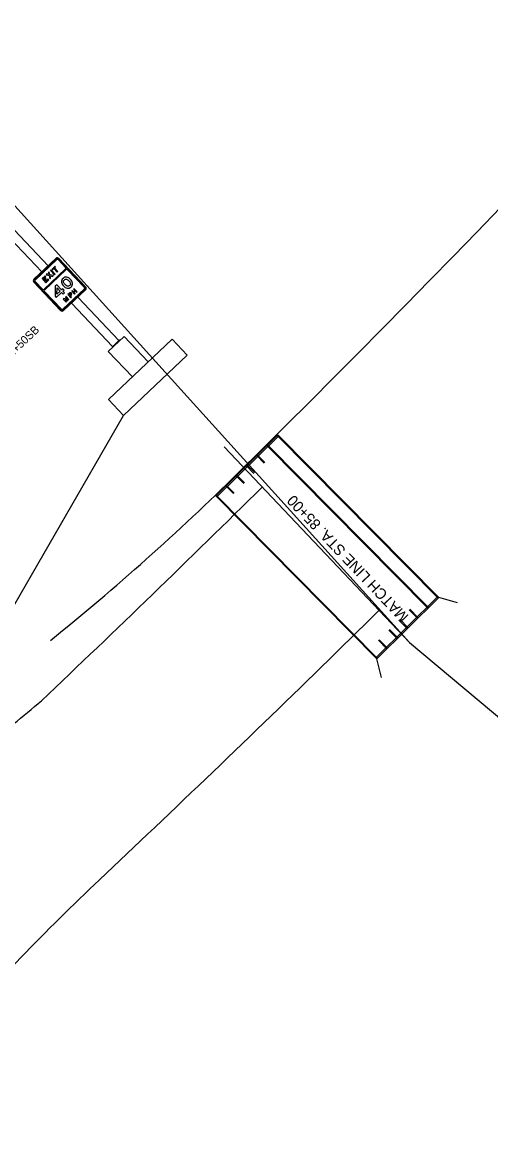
# Model space of a CAD drawing. Extents: x 1289840 to 1295361, y 220865 to 226414.
# Drawn here: x 1294139 to 1294486, y 224717 to 225540 of the extents above; entities that cross this region are included whole.
import ezdxf

# ---------------------------------------------------------------- set-up
doc = ezdxf.new("R2010")
doc.units = 0
for name, color, linetype in [('5', 7, 'Continuous'), ('Plan Notes', 7, 'Continuous'), ('R_Annotation', 7, 'Continuous'), ('R_Drainage', 7, 'Continuous'), ('R_No Plot', 7, 'Continuous'), ('R_Proposed Road', 7, 'Continuous'), ('S_MISC_STRUCTURES', 7, 'Continuous'), ('SIGNS', 7, 'Continuous')]:
    doc.layers.add(name, color=color, linetype=linetype)

msp = doc.modelspace()

# ---------------------------------------------------------------- linework, layer by layer
at = {"layer": '5'}
msp.add_line((1294425.84, 225079.29), (1294288.26, 225224.45), dxfattribs=at)
at = {"layer": 'R_Drainage'}
for p, q in [((1294328.06, 225233.41), (1294282.12, 225188.02)), ((1294328.76, 225232.7), (1294282.82, 225187.31)), ((1294327.64, 225233), (1294446.96, 225112.23)), ((1294447.38, 225112.64), (1294328.06, 225233.41)), ((1294320, 225225.44), (1294439.31, 225104.68)), ((1294320.53, 225225.97), (1294439.85, 225105.2)), ((1294312.47, 225218.01), (1294318.06, 225212.34)), ((1294312.88, 225218.42), (1294318.48, 225212.75)), ((1294297.71, 225203.42), (1294303.3, 225197.76)), ((1294304.82, 225210.45), (1294310.42, 225204.79)), ((1294305.35, 225210.98), (1294310.95, 225205.31)), ((1294289.64, 225195.46), (1294295.24, 225189.79)), ((1294290.06, 225195.87), (1294295.66, 225190.2)), ((1294297.17, 225202.9), (1294302.77, 225197.23)), ((1294401.43, 225067.25), (1294282.12, 225188.02)), ((1294282.53, 225188.43), (1294401.85, 225067.66)), ((1294446.67, 225113.35), (1294400.73, 225067.96)), ((1294447.38, 225112.64), (1294401.43, 225067.25)), ((1294461.3, 225108.82), (1294447.38, 225112.64)), ((1294424.67, 225090.21), (1294418.48, 225096.48)), ((1294431.79, 225097.24), (1294425.6, 225103.5)), ((1294432.2, 225097.65), (1294426.01, 225103.91)), ((1294416.49, 225082.13), (1294410.3, 225088.39)), ((1294417.02, 225082.65), (1294410.83, 225088.92)), ((1294424.14, 225089.68), (1294417.95, 225095.95)), ((1294408.96, 225074.69), (1294402.77, 225080.95)), ((1294409.38, 225075.1), (1294403.19, 225081.36)), ((1294405.09, 225053.28), (1294401.43, 225067.25))]:
    msp.add_line(p, q, dxfattribs=at)
for centre, radius, start, end in [((1286302.67, 233302.78), 11380.16, 314.636938, 322.750132), ((1292982.97, 226537.28), 1872.36, 308.9286, 314.63694)]:
    msp.add_arc(centre, radius, start, end, dxfattribs=at)
at = {"layer": 'R_No Plot'}
msp.add_lwpolyline([(1293463.51, 223873.73), (1293451.02, 223927.27), (1293084.88, 224313.59), (1293049.18, 224285.32), (1292886.4, 224457.07), (1293263.31, 224814.29), (1294021.34, 225526.85), (1294425.84, 225079.29), (1294588.32, 224942.91), (1294719.88, 224769.04), (1294177.05, 224254.57), (1293865.38, 223959.18), (1293708.84, 223976.93), (1293583.27, 224083.83), (1293485.04, 224003.92), (1293450.74, 223971.87), (1293580.16, 223892.04), (1293536.69, 223828.17)], close=True, dxfattribs=at)
at = {"layer": 'R_Proposed Road'}
msp.add_line((1294231.45, 224936.96), (1294195.79, 224903.17), dxfattribs=at)
for centre, radius, start, end in [((1286302.67, 233302.78), 11400.16, 313.519633, 314.664888), ((1286302.67, 233302.78), 11526.16, 313.463611, 314.651754), ((1292930.84, 226486.2), 1896.36, 308.48879, 310.12096), ((1295500.29, 223526.77), 1896.36, 133.46361, 138.41583)]:
    msp.add_arc(centre, radius, start, end, dxfattribs=at)
at = {"layer": 'S_MISC_STRUCTURES'}
for p, q in [((1294157.72, 225358.81), (1294084.18, 225436.41)), ((1294153.01, 225354.34), (1294079.46, 225431.94)), ((1294210.26, 225303.38), (1294180.08, 225335.22)), ((1294205.54, 225298.91), (1294175.36, 225330.75)), ((1294202.32, 225295.26), (1294214.11, 225306.43)), ((1294202.51, 225259.62), (1294249.69, 225304.33)), ((1294205.17, 225298.55), (1294210.67, 225303.76)), ((1294205.44, 225298.26), (1294210.94, 225303.48)), ((1294210.74, 225303.29), (1294205.63, 225298.45)), ((1294210.94, 225303.48), (1294210.67, 225303.76)), ((1294232, 225287.56), (1294214.11, 225306.43)), ((1294249.69, 225304.33), (1294260.87, 225292.54)), ((1294220.2, 225276.39), (1294202.32, 225295.26)), ((1294205.44, 225298.26), (1294205.17, 225298.55)), ((1294205.63, 225298.45), (1294205.66, 225298.42)), ((1294213.69, 225247.82), (1294260.87, 225292.54)), ((1294202.51, 225259.62), (1294213.69, 225247.82)), ((1294052.63, 224968.64), (1294213.69, 225247.82))]:
    msp.add_line(p, q, dxfattribs=at)
msp.add_lwpolyline([(1294205.66, 225298.42), (1294210.77, 225303.27), (1294210.74, 225303.29)], dxfattribs=at)
at = {"layer": 'SIGNS'}
for p, q in [((1294163.49, 225364.28), (1294147.24, 225348.87)), ((1294163.49, 225364.28), (1294147.24, 225348.87)), ((1294147.51, 225348.58), (1294163.77, 225363.99)), ((1294148.07, 225348.19), (1294164.13, 225363.41)), ((1294163.49, 225364.28), (1294163.49, 225364.28)), ((1294163.49, 225364.28), (1294163.49, 225364.28)), ((1294165.07, 225363.39), (1294170.76, 225357.39)), ((1294165.47, 225363.94), (1294185.28, 225343.04)), ((1294185.57, 225343.32), (1294165.76, 225364.22)), ((1294185.57, 225343.32), (1294165.76, 225364.22)), ((1294155.43, 225351.39), (1294153.25, 225349.31)), ((1294155.43, 225351.39), (1294153.25, 225349.31)), ((1294170.74, 225356.45), (1294154.67, 225341.22)), ((1294155.13, 225340.74), (1294171.19, 225355.96)), ((1294155.93, 225350.86), (1294155.43, 225351.39)), ((1294155.93, 225350.86), (1294155.43, 225351.39)), ((1294156.88, 225352.75), (1294156.33, 225352.23)), ((1294156.88, 225352.75), (1294156.33, 225352.23)), ((1294156.33, 225352.23), (1294158.52, 225351.66)), ((1294156.33, 225352.23), (1294158.52, 225351.66)), ((1294158.37, 225352.37), (1294156.88, 225352.75)), ((1294158.37, 225352.37), (1294156.88, 225352.75)), ((1294158.62, 225354.4), (1294158.07, 225353.88)), ((1294158.62, 225354.4), (1294158.07, 225353.88)), ((1294158.07, 225353.88), (1294158.37, 225352.37)), ((1294158.07, 225353.88), (1294158.37, 225352.37)), ((1294158.52, 225351.66), (1294159.05, 225349.04)), ((1294158.52, 225351.66), (1294159.05, 225349.04)), ((1294159.07, 225352.19), (1294158.62, 225354.4)), ((1294159.07, 225352.19), (1294158.62, 225354.4)), ((1294161.66, 225351.52), (1294159.07, 225352.19)), ((1294161.66, 225351.52), (1294159.07, 225352.19)), ((1294159.6, 225349.56), (1294159.21, 225351.49)), ((1294159.21, 225351.49), (1294161.11, 225350.99)), ((1294159.6, 225349.56), (1294159.21, 225351.49)), ((1294159.21, 225351.49), (1294161.11, 225350.99)), ((1294160, 225355.71), (1294159.47, 225355.21)), ((1294160, 225355.71), (1294159.47, 225355.21)), ((1294159.47, 225355.21), (1294162.35, 225352.18)), ((1294159.47, 225355.21), (1294162.35, 225352.18)), ((1294162.88, 225352.67), (1294160, 225355.71)), ((1294162.88, 225352.67), (1294160, 225355.71)), ((1294162.88, 225358.45), (1294160.65, 225356.33)), ((1294162.88, 225358.45), (1294160.65, 225356.33)), ((1294160.65, 225356.33), (1294161.09, 225355.86)), ((1294160.65, 225356.33), (1294161.09, 225355.86)), ((1294161.09, 225355.86), (1294161.97, 225356.69)), ((1294161.09, 225355.86), (1294161.97, 225356.69)), ((1294161.11, 225350.99), (1294161.66, 225351.52)), ((1294161.11, 225350.99), (1294161.66, 225351.52)), ((1294161.97, 225356.69), (1294164.41, 225354.12)), ((1294161.97, 225356.69), (1294164.41, 225354.12)), ((1294162.35, 225352.18), (1294162.88, 225352.67)), ((1294162.35, 225352.18), (1294162.88, 225352.67)), ((1294162.5, 225357.19), (1294163.33, 225357.98)), ((1294162.5, 225357.19), (1294163.33, 225357.98)), ((1294164.93, 225354.62), (1294162.5, 225357.19)), ((1294164.93, 225354.62), (1294162.5, 225357.19)), ((1294163.33, 225357.98), (1294162.88, 225358.45)), ((1294163.33, 225357.98), (1294162.88, 225358.45)), ((1294164.41, 225354.12), (1294164.93, 225354.62)), ((1294164.41, 225354.12), (1294164.93, 225354.62)), ((1294172.14, 225355.94), (1294184.7, 225342.68)), ((1294147.18, 225346.61), (1294147.18, 225346.61)), ((1294147.18, 225346.61), (1294147.18, 225346.61)), ((1294147.18, 225346.61), (1294166.99, 225325.71)), ((1294147.18, 225346.61), (1294166.99, 225325.71)), ((1294167.28, 225325.98), (1294147.47, 225346.88)), ((1294153.73, 225341.25), (1294148.04, 225347.25)), ((1294153.25, 225349.31), (1294156.13, 225346.27)), ((1294153.25, 225349.31), (1294156.13, 225346.27)), ((1294154.27, 225349.29), (1294155.93, 225350.86)), ((1294154.27, 225349.29), (1294155.93, 225350.86)), ((1294154.82, 225348.7), (1294154.27, 225349.29)), ((1294154.82, 225348.7), (1294154.27, 225349.29)), ((1294155.73, 225349.55), (1294154.82, 225348.7)), ((1294155.73, 225349.55), (1294154.82, 225348.7)), ((1294155.32, 225348.18), (1294156.22, 225349.03)), ((1294155.32, 225348.18), (1294156.22, 225349.03)), ((1294156.15, 225347.3), (1294155.32, 225348.18)), ((1294156.15, 225347.3), (1294155.32, 225348.18)), ((1294156.22, 225349.03), (1294155.73, 225349.55)), ((1294156.22, 225349.03), (1294155.73, 225349.55)), ((1294156.13, 225346.27), (1294158.36, 225348.39)), ((1294156.13, 225346.27), (1294158.36, 225348.39)), ((1294157.86, 225348.92), (1294156.15, 225347.3)), ((1294157.86, 225348.92), (1294156.15, 225347.3)), ((1294158.36, 225348.39), (1294157.86, 225348.92)), ((1294158.36, 225348.39), (1294157.86, 225348.92)), ((1294159.05, 225349.04), (1294159.6, 225349.56)), ((1294159.05, 225349.04), (1294159.6, 225349.56)), ((1294185.57, 225343.32), (1294185.57, 225343.32)), ((1294185.57, 225343.32), (1294185.57, 225343.32)), ((1294154.67, 225341.22), (1294154.67, 225341.22)), ((1294154.67, 225341.22), (1294154.67, 225341.22)), ((1294167.67, 225326.54), (1294155.1, 225339.79)), ((1294184.68, 225341.74), (1294168.61, 225326.51)), ((1294185.23, 225341.34), (1294168.97, 225325.94)), ((1294169.25, 225325.64), (1294185.51, 225341.05)), ((1294169.25, 225325.64), (1294185.51, 225341.05)), ((1294168.61, 225326.51), (1294168.61, 225326.51)), ((1294168.61, 225326.51), (1294168.61, 225326.51)), ((1294169.25, 225325.64), (1294169.25, 225325.64)), ((1294169.25, 225325.64), (1294169.25, 225325.64))]:
    msp.add_line(p, q, dxfattribs=at)
for points in [[(1294163.83, 225335.37), (1294167.61, 225338.95), (1294168.79, 225337.7), (1294169.87, 225338.72), (1294168.68, 225339.97), (1294169.58, 225340.82), (1294168.65, 225341.81), (1294167.75, 225340.96), (1294164.11, 225344.8), (1294163.03, 225343.77), (1294162.9, 225336.34), (1294163.83, 225335.37)], [(1294174.3, 225348.77), (1294173.67, 225349.35), (1294173.01, 225349.82), (1294172.34, 225350.15), (1294171.65, 225350.35), (1294170.87, 225350.4), (1294170.13, 225350.27), (1294169.43, 225349.95), (1294168.78, 225349.45), (1294168.23, 225348.82), (1294167.88, 225348.13), (1294167.71, 225347.4), (1294167.73, 225346.61), (1294167.89, 225345.9), (1294168.19, 225345.21), (1294168.61, 225344.53), (1294169.17, 225343.87), (1294169.8, 225343.28), (1294170.45, 225342.81), (1294171.13, 225342.47), (1294171.82, 225342.26), (1294172.62, 225342.18), (1294173.37, 225342.29), (1294174.07, 225342.6), (1294174.72, 225343.1), (1294175.28, 225343.75), (1294175.65, 225344.44), (1294175.82, 225345.19), (1294175.79, 225345.98), (1294175.62, 225346.69), (1294175.31, 225347.39), (1294174.87, 225348.08), (1294174.3, 225348.77)], [(1294173.22, 225347.69), (1294173.84, 225346.87), (1294174.2, 225346.01), (1294174.28, 225345.49), (1294174.22, 225345.02), (1294174.04, 225344.6), (1294173.73, 225344.22), (1294173.32, 225343.91), (1294172.88, 225343.74), (1294172.41, 225343.7), (1294171.9, 225343.79), (1294171.07, 225344.18), (1294170.26, 225344.88), (1294169.62, 225345.72), (1294169.26, 225346.59), (1294169.19, 225347.1), (1294169.26, 225347.58), (1294169.45, 225348.01), (1294169.77, 225348.4), (1294170.18, 225348.71), (1294170.63, 225348.88), (1294171.1, 225348.92), (1294171.6, 225348.82), (1294172.41, 225348.4), (1294173.22, 225347.69)], [(1294164.29, 225337.68), (1294164.35, 225342.39), (1294166.67, 225339.94), (1294164.29, 225337.68)], [(1294174.63, 225335.15), (1294175.03, 225335.53), (1294174.17, 225336.44), (1294174.83, 225337.07), (1294175.04, 225337.3), (1294175.17, 225337.55), (1294175.22, 225337.8), (1294175.2, 225338.07), (1294175.12, 225338.31), (1294174.98, 225338.51), (1294174.83, 225338.64), (1294174.66, 225338.73), (1294174.49, 225338.78), (1294174.29, 225338.79), (1294174.1, 225338.77), (1294173.92, 225338.71), (1294173.75, 225338.62), (1294173.59, 225338.49), (1294172.47, 225337.43), (1294174.63, 225335.15)], [(1294173.8, 225336.83), (1294173.25, 225337.41), (1294173.93, 225338.05), (1294174.08, 225338.16), (1294174.24, 225338.21), (1294174.41, 225338.19), (1294174.56, 225338.09), (1294174.64, 225337.95), (1294174.65, 225337.79), (1294174.6, 225337.63), (1294174.5, 225337.49), (1294173.8, 225336.83)]]:
    msp.add_lwpolyline(points, dxfattribs=at)
for points in [[(1294171.06, 225331.77), (1294171.47, 225332.15), (1294170.14, 225333.56), (1294172.14, 225332.79), (1294171.49, 225334.84), (1294172.82, 225333.44), (1294173.22, 225333.82), (1294171.06, 225336.1), (1294170.66, 225335.71), (1294171.25, 225333.73), (1294169.3, 225334.43), (1294168.9, 225334.05)], [(1294177.41, 225337.79), (1294177.81, 225338.17), (1294176.86, 225339.17), (1294177.89, 225340.14), (1294178.84, 225339.14), (1294179.27, 225339.55), (1294177.11, 225341.83), (1294176.68, 225341.42), (1294177.5, 225340.55), (1294176.47, 225339.58), (1294175.65, 225340.45), (1294175.25, 225340.06)]]:
    msp.add_lwpolyline(points, close=True, dxfattribs=at)
for centre, radius, start, end in [((1294164.59, 225363.12), 1.6, 43.46361, 133.46382), ((1294164.59, 225363.12), 1.6, 43.46361, 133.46382), ((1294164.59, 225363.12), 1.2, 43.46361, 133.46382), ((1294164.59, 225362.93), 0.667, 43.46361, 133.46382), ((1294170.28, 225356.93), 0.667, 313.46367, 43.46388), ((1294171.65, 225355.48), 0.667, 43.46361, 133.46382), ((1294148.34, 225347.71), 1.6, 133.46382, 223.46346), ((1294148.34, 225347.71), 1.6, 133.46382, 223.46346), ((1294148.34, 225347.71), 1.2, 133.46382, 223.46346), ((1294148.53, 225347.7), 0.667, 133.46382, 223.46346), ((1294184.41, 225342.22), 1.2, 313.46367, 43.46388), ((1294184.41, 225342.22), 1.6, 313.46367, 43.46388), ((1294184.41, 225342.22), 1.6, 313.46367, 43.46388), ((1294154.21, 225341.7), 0.667, 223.46346, 313.46367), ((1294155.59, 225340.25), 0.667, 133.46382, 223.46346), ((1294184.22, 225342.22), 0.667, 313.46367, 43.46388), ((1294168.15, 225326.81), 1.6, 223.46346, 313.46367), ((1294168.15, 225326.81), 1.6, 223.46346, 313.46367), ((1294168.15, 225326.81), 1.2, 223.46346, 313.46367), ((1294168.15, 225326.99), 0.667, 223.46346, 313.46367)]:
    msp.add_arc(centre, radius, start, end, dxfattribs=at)

# ---------------------------------------------------------------- texts
at = {"layer": 'Plan Notes'}
msp.add_text('MATCH LINE STA. 85+00', height=8, rotation=133.46361, dxfattribs=at).set_placement((1294425.64, 225098.98))
at = {"layer": 'R_Annotation'}
msp.add_text('SS-057-43-STA81+50SB', height=6, rotation=43.43866, dxfattribs=at).set_placement((1294086.46, 225248.84))

doc.saveas('drawing.dxf')
